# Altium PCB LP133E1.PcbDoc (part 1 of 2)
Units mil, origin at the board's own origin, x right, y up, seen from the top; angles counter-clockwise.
Board outline 3991.15 x 4704.13 mil, 4 copper layers (Top Layer, L02_GND1, L03_GND2, Bottom Layer), stack 58.396 mil thick; 74 components, 22 nets, 180 pads, 42 vias.
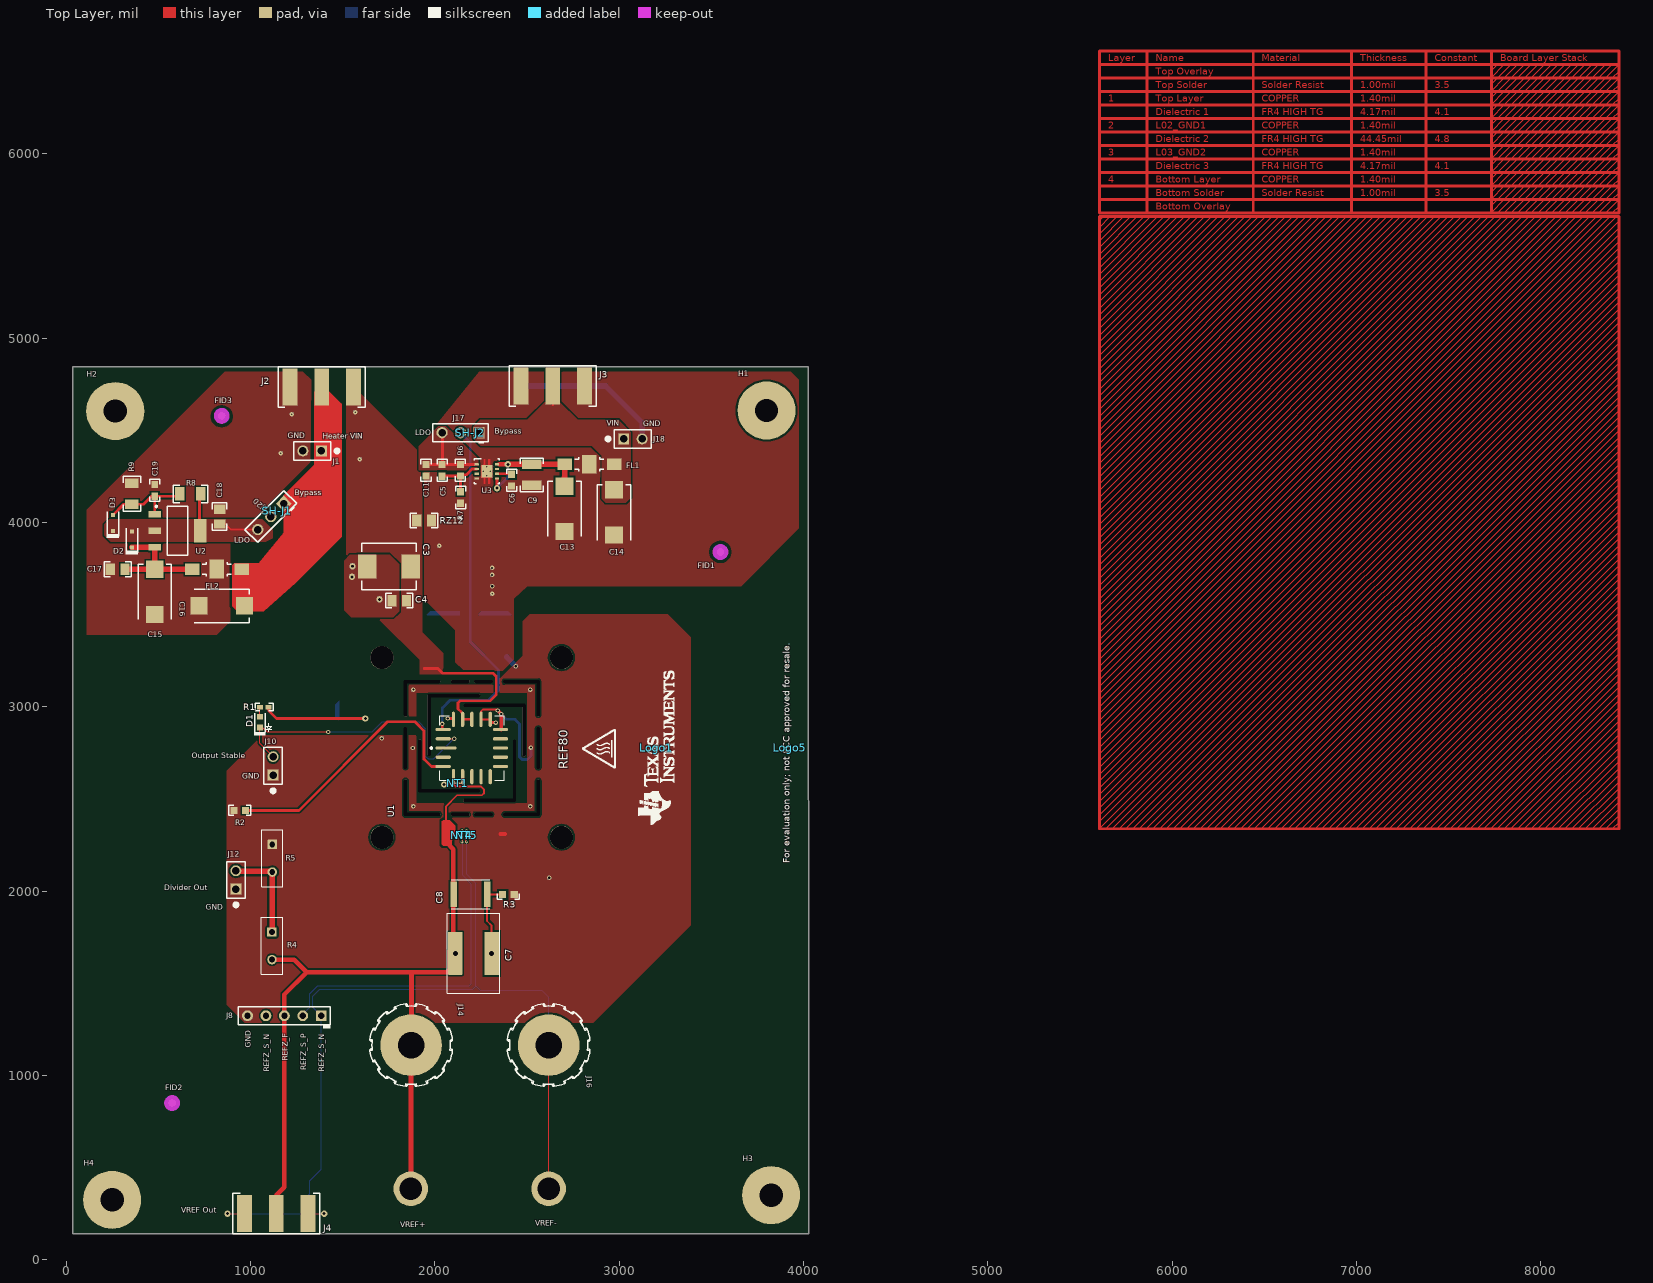
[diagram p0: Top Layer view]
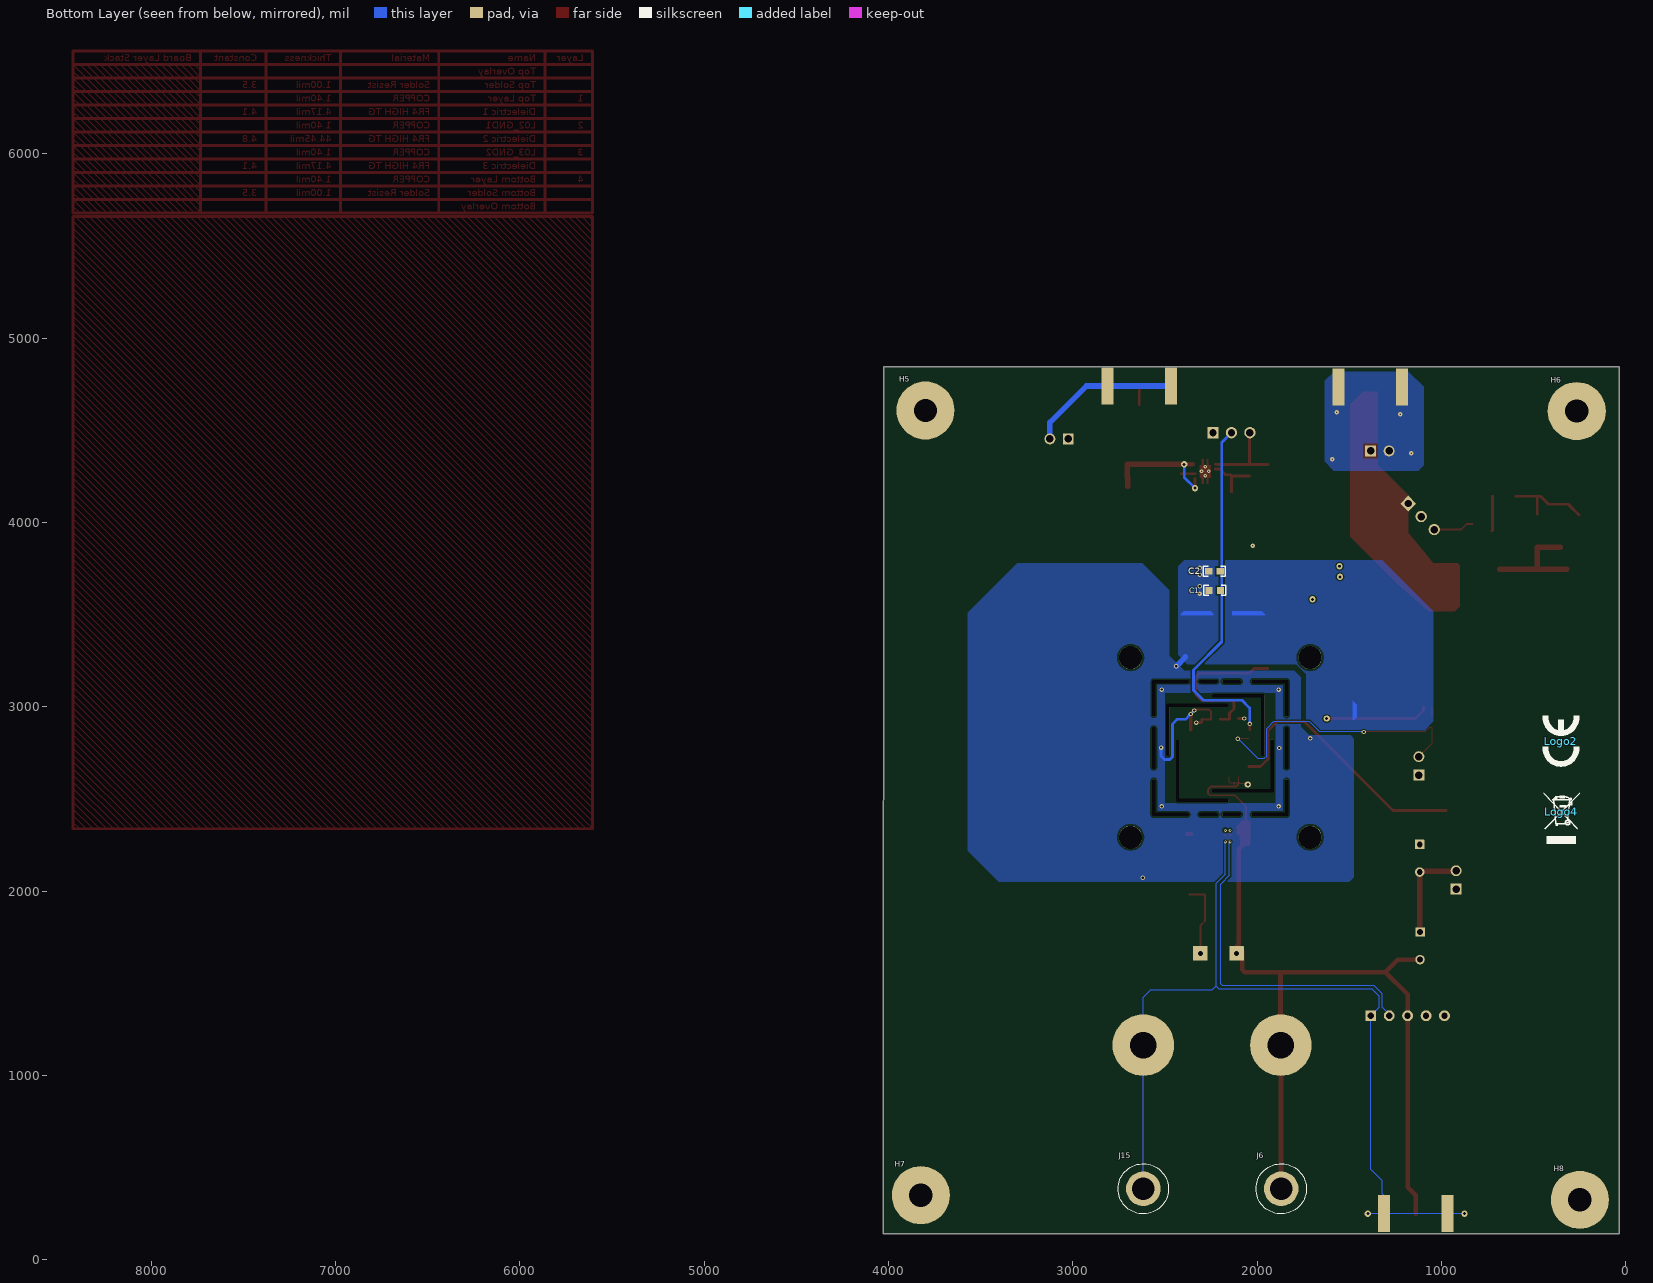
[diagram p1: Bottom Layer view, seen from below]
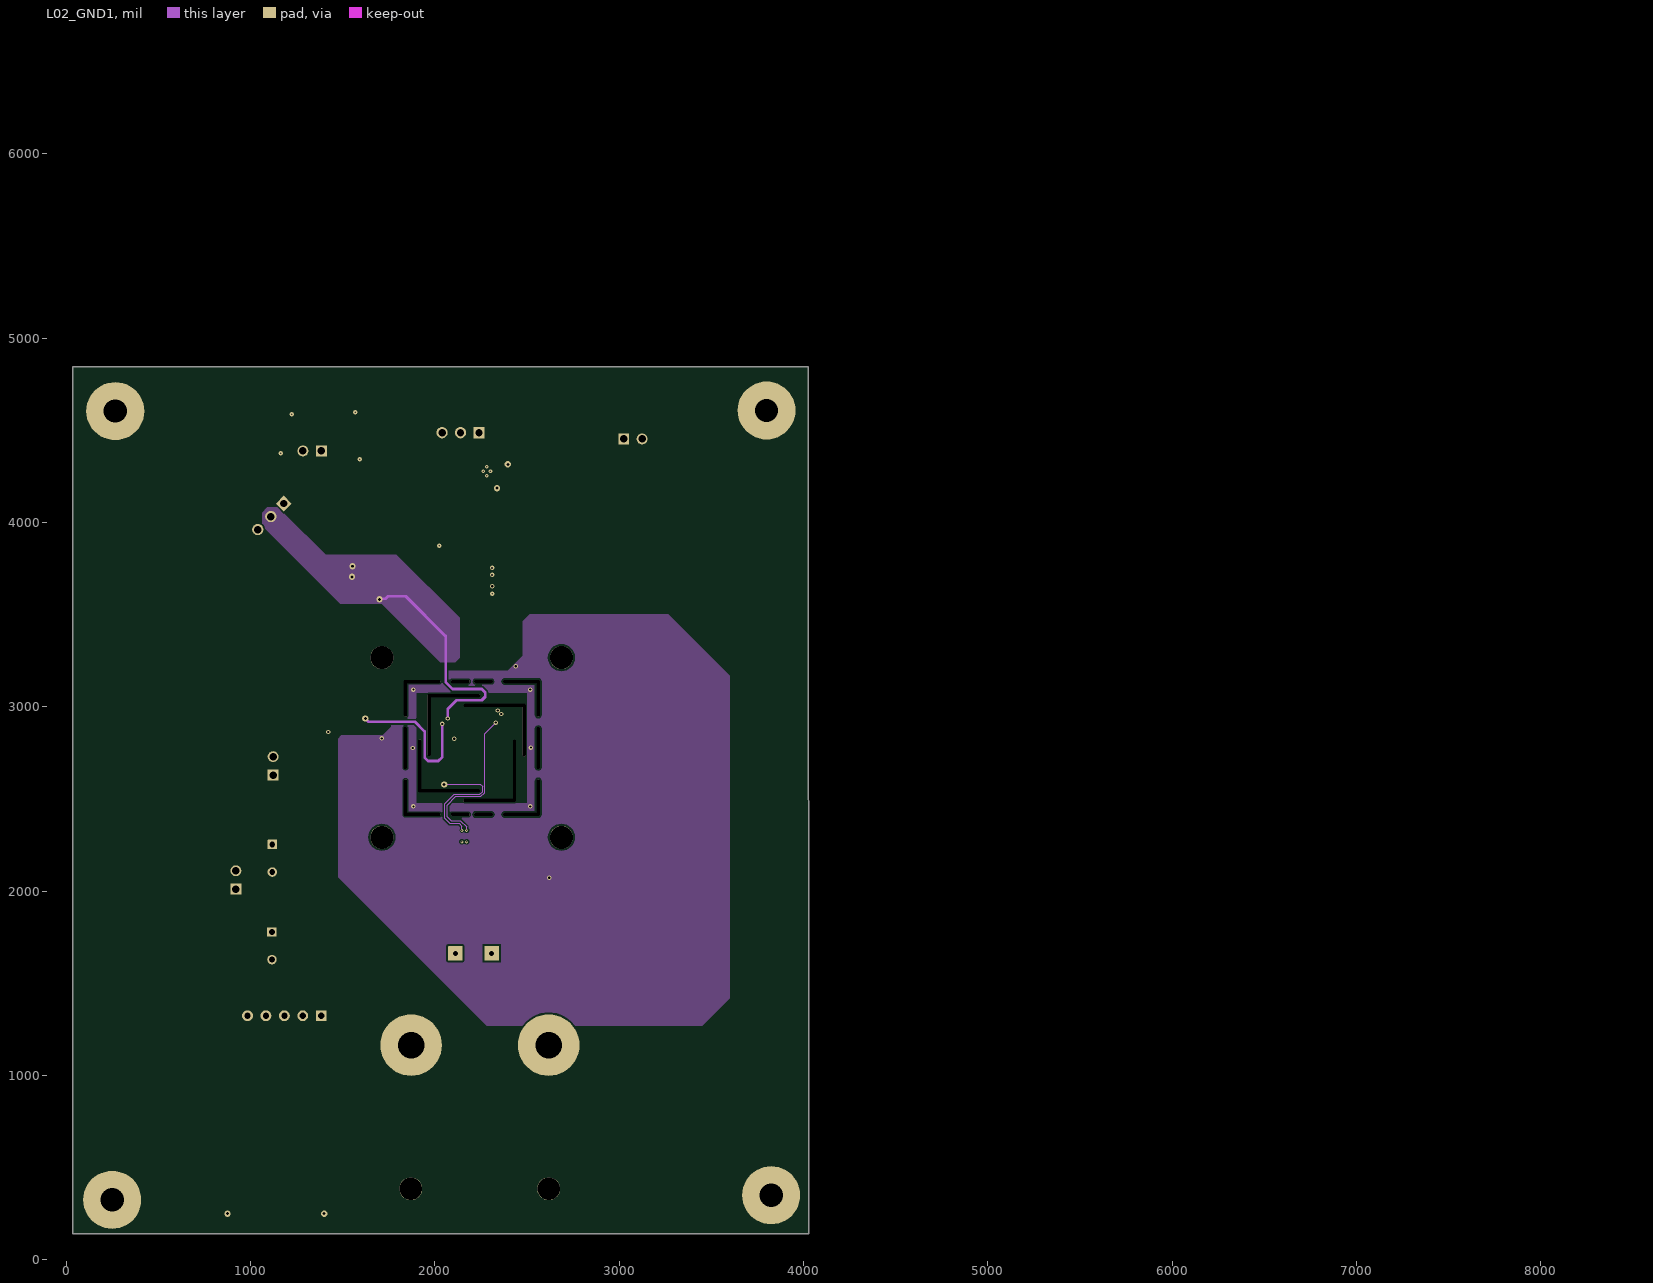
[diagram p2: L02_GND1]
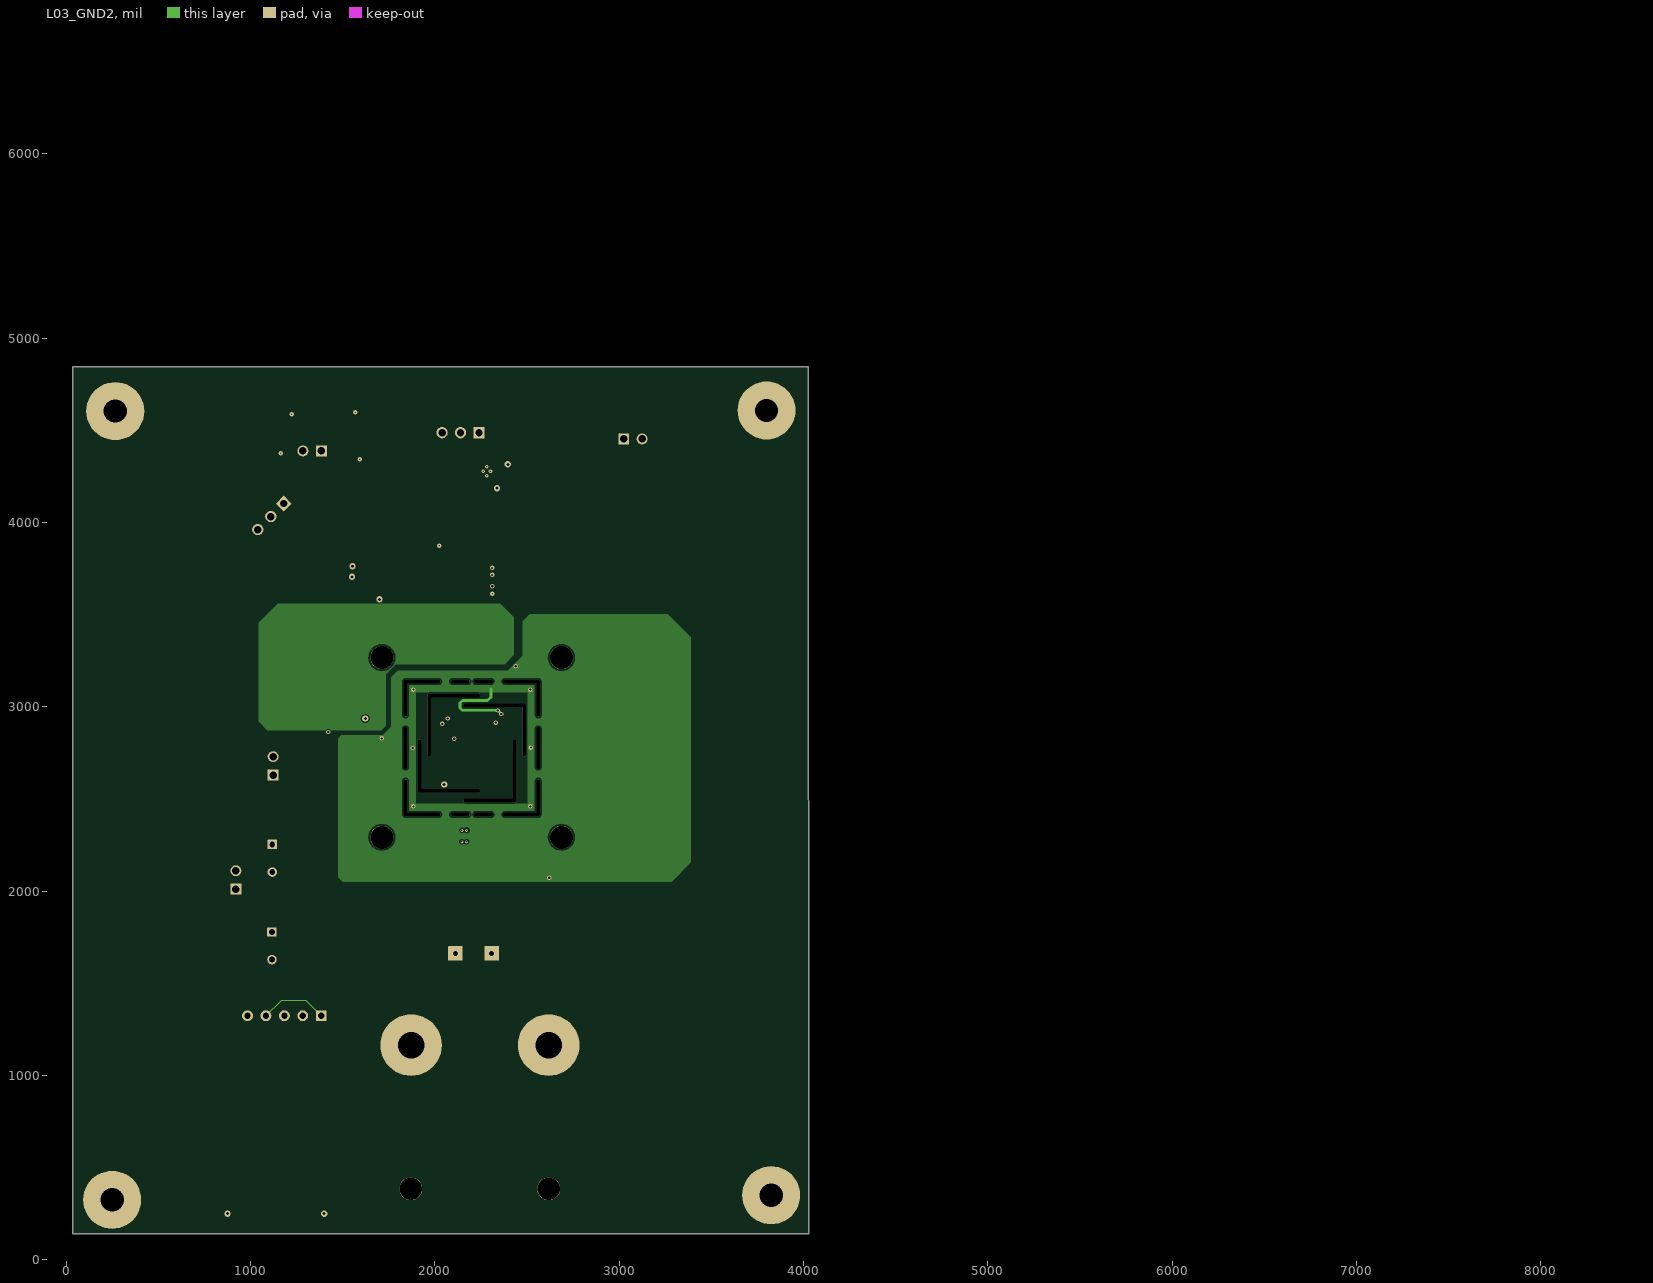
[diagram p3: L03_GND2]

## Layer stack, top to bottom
Top Solder: solder mask 1, Solder Resist, Dk 3.5
Top Layer: signal copper 1.4
Dielectric 1: prepreg 4.174, FR4 HIGH TG, Dk 4.1
L02_GND1: signal copper 1.4
Dielectric 2: core 44.448, FR4 HIGH TG, Dk 4.8
L03_GND2: signal copper 1.4
Dielectric 3: prepreg 4.174, FR4 HIGH TG, Dk 4.1
Bottom Layer: signal copper 1.4
Bottom Solder: solder mask 1, Solder Resist, Dk 3.5

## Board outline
37.25,140 36.73,4844.13 4027.14,4844.07 4027.88,140

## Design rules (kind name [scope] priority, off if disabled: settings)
AcuteAngle [All] p1: minimum=4.50000000000000E+0001 checktracksonly=FALSE
AssemblyTestPointUsage [All] p1: valid=2
BoardOutlineClearance DUT [WithinRoom('RoomDefinition')] p1: gap=5 ignorepadtopadclearanceinfootprint=FALSE
BoardOutlineClearance BoardOutlineClearance_MountingHoles [OnCopper and InComponentClass('Mounting Holes')] p2: gap=39.37 ignorepadtopadclearanceinfootprint=FALSE
BoardOutlineClearance BoardOutlineClearance_Poly [OnCopper and IsPoly] p3: gap=25 ignorepadtopadclearanceinfootprint=FALSE
BoardOutlineClearance [OnCopper and Not InComponentClass('Logo') and not InComponentClass('FiducialMark') and not InRegion(1000,500,4000,800) and not InPoly] p4: gap=40 ignorepadtopadclearanceinfootprint=FALSE
Clearance PWR1 [InNet('VIN_HTR') vs OnLayer('PWR1')] p1: gap=6 ignorepadtopadclearanceinfootprint=TRUE except(6.9: Via-Region; 7: Track-Region; 7.8: Fill-Region Region-Region; 8: Arc-Hole Track-Hole SMDPad-Hole THPad-Hole Via-Hole Fill-Hole Poly-Hole Region-Hole Text-Hole; 10: Arc-Poly Arc-Region SMDPad-Poly THPad-Poly THPad-Region Fill-Poly Poly-Poly Poly-Region; 15: Track-Poly)
Clearance [All] p2: gap=6 ignorepadtopadclearanceinfootprint=TRUE except(5: Track-Track Track-SMDPad SMDPad-Region Region-Region; 6.9: Via-Region; 7: Track-Region; 7.8: Fill-Region; 8: Arc-Hole SMDPad-Hole THPad-Region THPad-Hole Via-Hole Fill-Hole Poly-Hole Region-Hole Text-Hole; 9: Track-Hole; 10: Arc-Poly Arc-Region Track-Poly SMDPad-Poly THPad-Poly Fill-Poly Poly-Poly; 15: Poly-Region)
ComponentClearance ComponentClearance_MountingHoles_FiducialMarks [InComponentClass('Mounting Holes') vs InComponentClass('FiducialMark')] p1: gap=50 collisioncheckmode=3 verticalgap=10 showdistances=FALSE
ComponentClearance ComponentClearance_Shunt [InComponentClass('Header') vs InComponentClass('Shunt')] p2: gap=0 collisioncheckmode=3 verticalgap=0 showdistances=FALSE
ComponentClearance ComponentClearance_Logo [InComponentClass('Logo')] p3: gap=30 collisioncheckmode=3 verticalgap=10 showdistances=FALSE
ComponentClearance ComponentClearance_ScrewToNut [(HasFootprint('NY PMS 440 0025 PH')) vs (HasFootprint('Keystone_1902C'))] p4: gap=5 collisioncheckmode=3 verticalgap=10 showdistances=FALSE
ComponentClearance ComponentClearance_MountingHoles [InComponentClass('Mounting Holes')] p5: gap=100 collisioncheckmode=3 verticalgap=100000 showdistances=FALSE
ComponentClearance ComponentClearance_SmallPassives [HasFootprint('0201*') or HasFootprint('0402*') or HasFootprint('0508') or HasFootprint('0603*') or HasFootprint('0612') or HasFootprint('0805*') or HasFootprint('0815*') or HasFootprint('0830*') or HasFootprint('1206*') or HasFootprint('1210*') or HasFootprint('1808*') or HasFootprint('1812*') or HasFootprint('1825*') or HasFootprint('2010*') or HasFootprint('2220*') or HasFootprint('2225*') or HasFootprint('2512*') or HasFootprint('2728*') or HasFootprint('3518*') vs HasFootprint('0201*') or HasFootprint('0402*') or HasFootprint('0508') or HasFootprint('0603*') or HasFootprint('0612') or HasFootprint('0805*') or HasFootprint('0815*') or HasFootprint('0830*') or HasFootprint('1206*') or HasFootprint('1210*') or HasFootprint('1808*') or HasFootprint('1812*') or HasFootprint('1825*') or HasFootprint('2010*') or HasFootprint('2220*') or HasFootprint('2225*') or HasFootprint('2512*') or HasFootprint('2728*') or HasFootprint('3518*')] p6: gap=14.96 collisioncheckmode=3 verticalgap=10 showdistances=FALSE
ComponentClearance ComponentClearance_THtoSMT [IsThruComponent vs IsSMTComponent] p7: gap=30 collisioncheckmode=3 verticalgap=30 showdistances=FALSE
ComponentClearance ComponentClearance_THtoTH [IsThruComponent vs IsThruComponent] p8: gap=20 collisioncheckmode=3 verticalgap=30 showdistances=FALSE
ComponentClearance [All] p9: gap=20 collisioncheckmode=3 verticalgap=10 showdistances=FALSE
DiffPairsRouting [All] p1: maxlimit=11.47 minlimit=11.47 mostfreqgap=11.47 toplayer_minwidth=6.53 toplayer_maxwidth=6.53 toplayer_prefwidth=6.53 midlayer1_minwidth=6.53 midlayer1_maxwidth=6.53 midlayer1_prefwidth=6.53 midlayer2_minwidth=6.53 midlayer2_maxwidth=6.53 midlayer2_prefwidth=6.53 bottomlayer_minwidth=6.53 bottomlayer_maxwidth=6.53 bottomlayer_prefwidth=6.53 maxuncoupledlength=1000
FabricationTestPointUsage TestPointUsage [All] p1: valid=2 allowmultiple=FALSE
FabricationTestpoint Testpoint [All] p1: side=3 testpointundercomponent=TRUE minsize=40 maxsize=100 preferedsize=60 minholesize=0 maxholesize=40 preferedholesize=32 testpointgrid=1 allowsidetop=TRUE allowsidebottom=TRUE usegrid=TRUE gridtolerance=0.01
FanoutControl Fanout_LCC [IsLCC] p1: bgadir=Out bgaviamode=Centered fanoutstyle=Auto fanoutdirection=Alternating viagrid=1 // Fanout_LCC (Default Rule)
FanoutControl Fanout_BGA [IsBGA] p2: bgadir=Out bgaviamode=Centered fanoutstyle=Auto fanoutdirection=Alternating viagrid=1 // Fanout_BGA (Default Rule)
FanoutControl Fanout_Default [All] p4: bgadir=Out bgaviamode=Centered fanoutstyle=Auto fanoutdirection=Alternating viagrid=1 // Fanout_Default (Default Rule)
FanoutControl Fanout_Small [(CompPinCount < 5)] p5: bgadir=Out bgaviamode=Centered fanoutstyle=Auto fanoutdirection=OutThenIn viagrid=1 // Fanout_Small (Default Rule)
HoleSize [All] p1: absolutevalues=TRUE maxlimit=251 minlimit=7.87 maxpercent=80.000 minpercent=20.000
MinimumAnnularRing MinimumAnnularRing_ThermalPadVias [IsVia and InAnyComponent] p1: minimumring=5.91
MinimumAnnularRing [All] p2: minimumring=7.87
MinimumSolderMaskSliver MinimumSolderMaskSliver_Logo [InComponentClass('Logo') vs InComponentClass('Logo')] p1: minsoldermaskwidth=0.7
MinimumSolderMaskSliver [All] p2: minsoldermaskwidth=3.94
PlaneConnect [All] p1: planeconnectstyle=Relief reliefexpansion=10 reliefentries=4 reliefconductorwidth=10 reliefairgap=10
PolygonConnect [All] p1: connectstyle=Direct reliefconductorwidth=10 reliefentries=4 polygonreliefangle="90 Angle" airgapwidth=10
RoomDefinition LP133E1_Hardware [InComponentClass('LP133E1_Hardware')] p1: confinementstyle=ConfineIn formatcopy=TRUE lockcomponents=FALSE outline 291.49,1189.73 1196.62,1189.73 1196.62,301.8 291.49,301.8
RoutingVias ThermalPadVias [IsVia and InAnyComponent] p1: holewidth=7.87 width=19.68 viastyle="Through Hole" minholewidth=7.87 minwidth=19.68 maxholewidth=12.99 maxwidth=23.62
RoutingVias [All] p2: holewidth=16 width=34 viastyle="Through Hole" minholewidth=7.87 minwidth=24 maxholewidth=40 maxwidth=65
SMDEntry [All] p1: side=TRUE corner=TRUE anyangle=FALSE
SMDToCorner [All] p1: distance=0
SilkToBoardRegionClearance [Not ((IsComment or IsDesignator) And (Hide <> 'False')) and not InRegion(1000,500,4000,800)] p1:
SilkToSilkClearance SilkToSilkClearance_Pb-FreeLogo [(HasFootprint('Pb-Free_Overlay_Medium') OR HasFootprint('Pb-Free_Overlay_Small')) vs (HasFootprint('Pb-Free_Overlay_Medium') OR HasFootprint('Pb-Free_Overlay_Small'))] p1: silktosilkclearance=0
SilkToSilkClearance [All] p2: silktosilkclearance=3.94
SilkToSolderMaskClearance SilkToComponentPadClearance [(IsPad or IsFill or IsRegion) and InAnycomponent] p1: minsilkscreentomaskgap=5 clearancetoexposedcopper=TRUE
SilkToSolderMaskClearance "Silk to Solder Mask Opening" [All] p2: minsilkscreentomaskgap=3.94 clearancetoexposedcopper=FALSE
SolderMaskExpansion [All] p1: expansion=1.97 istentingtop=FALSE
UnRoutedNet [All] p1: checkbadconnections=TRUE
Width [All] p1: maxlimit=100 minlimit=6 preferedwidth=8 checkconnectedcopper=TRUE
14 further rules are at their usual default settings.

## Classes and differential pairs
component class "Mounting Holes": H1 H2 H3 H4
component class LP133E1_Hardware: !PCB FID1 FID2 FID3 H1 H2 H3 H4 H5 H6 H7 H8 Logo1 Logo2 Logo3 Logo4 Logo5 ZZ1 ZZ2 ZZ3 ZZ4
component class Header: J1 J8 J10 J12 J18
component class LP133E1: 1 C1 C2 C3 C4 C5 C6 C7 C8 C9 C11 C13 C14 C15 C16 C17 C18 C19 D1 D2 D3 FL1 FL2 J1 J2 J3 J4 J6 J8 J10 J12 J14 J15 J16 J17 J18 J20 NT1 NT4 NT5 R1 R2 R3 R4 R5 R6 R7 R8 R9 RZ12 SH-J1 SH-J2 U1 U2 U3
component class Logo: Logo1
component class FiducialMark: FID1 FID2 FID3
component class AssemblyNote: ZZ1 ZZ2 ZZ3 ZZ4

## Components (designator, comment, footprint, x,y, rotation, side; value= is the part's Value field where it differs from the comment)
C1 "GRJ188R71E105KE11D" 0603 2230.37,3631.07 r0 bottom value=1uF
C2 "CL10A104KA8NNNC" 0603 2232.18,3734.98 r0 bottom value=0.1uF
C3 "TAJV226K050RNJ" 7361-38 1751.94,3761.5 r0 top value=22uF
C4 "CL21B105KBFNFNE" 0805_HV 1807.42,3575.7 r0 top value=1uF
C5 "C0603C103F3GACTU" 0603 2039.83,4282.19 r270 top value=0.01uF
C6 "C0603C103F3GACTU" 0603 2416.66,4229.57 r270 top value=0.01uF
C7 "MKS2B051001N00JSSD" FP-MKS2B051001N00JSSD_RADIAL-MFG 2210.01,1662.11 r0 top value=10µF
C8 "16MU106MC44532" 1812 2192.95,1982.14 r0 top value=10UF
C9 "CL32B106KBJNNWE" 1210_270 2525.72,4257.87 r270 top value=10uF
C11 "GRM188R61E106KA73D" 0603 1952.46,4282.72 r270 top value=10uF
C13 "20TQC47MYF" 7343-20 2703.61,4073.84 r270 top value=47uF
C14 "20TQC47MYF" 7343-20 2972.54,4054.15 r270 top value=47uF
C15 "20TQC47MYF" 7343-20 480.92,3623.46 r270 top value=47uF
C16 "20TQC47MYF" 7343-20 844.21,3547.28 r180 top value=47uF
C17 "C2012X6S1H105K125AB" 0805_HV 279.85,3746.41 r180 top value=1uF
C18 "C2012X6S1H105K125AB" 0805_HV 832.63,4031.43 r90 top value=1uF
C19 "GRM188R61E106KA73D" 0603 480.92,4173.55 r270 top value=10uF
D1 "HSMA-C190" HSMx-C190_Amber 1051.45,2916.44 r270 top value=Amber
D2 "CUS10S30,H3F" SOD-323 357.15,3907.42 r90 top value=20V
D3 "CUS10S30,H3F" SOD-323 254.24,3996.98 r90 top value=20V
FID1 "Fiducial" Fiducial10-20 3549.88,3839.39 r0 top
FID2 "Fiducial" Fiducial10-20 575,850 r0 top
FID3 "Fiducial" Fiducial10-20 844.21,4578.04 r0 top
FL1 "NFE61PT472C1H9L" 2706 2838.69,4315.73 r0 top value=4700pF
FL2 "NFE61PT472C1H9L" 2706 818.15,3746.3 r0 top value=4700pF
H1 "NY PMS 440 0025 PH" "NY PMS 440 0025 PH" 3800,4607.26 r0 top
H2 "NY PMS 440 0025 PH" "NY PMS 440 0025 PH" 266.73,4603.97 r0 top
H3 "NY PMS 440 0025 PH" "NY PMS 440 0025 PH" 3825,350 r0 top
H4 "NY PMS 440 0025 PH" "NY PMS 440 0025 PH" 250,325 r0 top
H5 "1902C" Keystone_1902C 3800.13,4607.27 r180 bottom
H6 "1902C" Keystone_1902C 266.86,4603.98 r180 bottom
H7 "1902C" Keystone_1902C 3825.13,350.01 r180 bottom
H8 "1902C" Keystone_1902C 250.36,325.01 r180 bottom
J1 "5-146261-1" CONN_5-146261-1 1334.72,4387.76 r180 top
J2 "142-0701-851" EMERSON_142-0701-851 1386.76,4844.11 r0 top
J3 "142-0701-851" EMERSON_142-0701-851 2640.07,4850 r0 top
J4 "142-0701-851" EMERSON_142-0701-851 1140,140 r180 top
J6 "72918" FP-72918_CONNECTOR_BANANA_PLUG-MFG 1869.98,384.74 r180 bottom locked
J8 "800-10-005-10-001000" Mill-Max_800-10-005-10-001000 1184.11,1323.66 r180 top
J10 "5-146261-1" CONN_5-146261-1 1123.07,2679.12 r90 top
J12 "5-146261-1" CONN_5-146261-1 921.41,2060.17 r90 top
J14 "111-0702-001" Emerson_111-0702-001 1871.95,1164.22 r270 top
J15 "72918" FP-72918_CONNECTOR_BANANA_PLUG-MFG 2618.01,384.74 r180 bottom locked
J16 "111-0703-001" Emerson_111-0703-001 2618.01,1164.22 r270 top
J17 "HTSW-103-09-G-S" Samtec_HTSW-103-09-x-S 2139.83,4486.75 r180 top
J18 "5-146261-1" CONN_5-146261-1 3075,4452.98 r0 top
J20 "HTSW-103-09-G-S" Samtec_HTSW-103-09-x-S 1110.55,4031.79 r225 top
Logo1 "Texas Instruments" TI_Stacked_Overlay_Small 3201.87,2777.53 r90 top
Logo2 "CE Mark" CE_Mark_5mm 352.15,2812.45 r90 bottom
Logo3 "FCC disclaimer" FCC_disclaimer -3342.4,1916.61 r180 bottom
Logo4 "WEEE logo" WEEE_Minimum 350,2429.53 r180 bottom
Logo5 "FCC disclaimer" FCC_disclaimer 3925,2778.58 r90 top
NT1 "Net-Tie" Net-Tie_10mil 2124.6,2584.87 r0 top net-tie
NT4 "Net-Tie" Net-Tie_10mil 2147.04,2302.95 r270 top net-tie
NT5 "Net-Tie" Net-Tie_10mil 2172.83,2302.95 r270 top net-tie
R1 "CRCW04021K00JNED" 0402 1075.08,2997.93 r0 top value=1.0k
R2 "RT0603DRE07135KL" 0603 942.29,2437.68 r0 top value=135k
R3 "ERJ-3RQFR22V" 0603 2399.6,1982.14 r180 top value=0.22
R4 "Y0062100K000T9L" FP-Y0062100K000T9L_RADIAL-MFG 1116.69,1702.91 r270 top value=100k
R5 "Y0062100K000T9L" FP-Y0062100K000T9L_RADIAL-MFG 1118.63,2177.93 r270 top value=100k
R6 "RC0603FR-0739KL" 0603 2139.34,4283.27 r90 top value=39.0k
R7 "RC0603JR-073K3L" 0603 2139.83,4134.86 r90 top value=3.3k
R8 "CRCW1206100RFKEA" 1206 674.45,4154.67 r0 top value=100
R9 "CRCW12061K10JNEA" 1206 357.09,4155.83 r270 top value=1.1k
RZ12 "CRCW08050000Z0EA" 0805_HV 1941.75,4010.22 r180 top value=0
SH-J1 "QPC02SXGN-RC" FP-QPC02SXGN-RC_JUMPER-MFG 1144.78,4061.97 r45 top
SH-J2 "QPC02SXGN-RC" FP-QPC02SXGN-RC_JUMPER-MFG 2192.65,4487.72 r180 top
U1 "REF80000A1NAJ" NAJ0020A-IPC_C 2201.15,2776.12 r90 top locked
U2 "LM317AEMP/NOPB" DCY0004A_N 603.95,3954.66 r0 top
U3 "TPS7A4901DRBR" DRB0008A 2282.44,4276.77 r0 top
ZZ1 "This Assembly Note is for PCB labels only" AssemblyNoteLabel -1560.47,-1146.06 r0 top
ZZ2 "These assemblies are ESD sensitive, ESD precautions shall be observed." AssemblyNote -1560.47,-1254.94 r0 top
ZZ3 "These assemblies must be clean and free from flux and all contaminants. Use of no clean flux is not acceptable." AssemblyNote -1560.47,-1343.5 r0 top
ZZ4 "These assemblies must comply with workmanship standards IPC-A-610 Class 2, unless otherwise specified." AssemblyNote -1560.47,-1432.06 r0 top

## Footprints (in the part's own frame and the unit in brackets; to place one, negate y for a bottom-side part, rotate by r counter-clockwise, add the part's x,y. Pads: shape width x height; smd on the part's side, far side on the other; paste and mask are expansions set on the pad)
0402 [mm] "0402 from SM-752 data"
  rect 0.8x0.6 smd: 1(-0.6,0) 2(0.6,0)
  silkscreen extent -1.22,-0.52 1.22,0.52, body extent -0.55,-0.3 0.55,0.3, height 0.6
0603 [mm] "0603 from SM-752 data"
  rect 1x0.95 smd: 1(-0.8,0) 2(0.8,0)
  silkscreen extent -1.52,-0.69 1.52,0.69, body extent -0.87,-0.47 0.87,0.47, height 1
0805_HV [mil] "0805 with 30mil clearance between pads"
  rect 50x63 smd: 1(-40,0) 2(40,0)
  silkscreen extent -74,-40 74,40, body extent -43,-29 43,29, height 57
1206 [mm] "1206 from SM-752 data"
  rect 1.3x1.85 smd: 1(-1.45,0) 2(1.45,0)
  silkscreen extent -2.4,-1.21 2.4,1.21, body extent -1.7,-0.9 1.7,0.9, height 1.35
1210_270 [mm] "1210"
  rect 1.3x2.7 smd: 1(-1.45,0) 2(1.45,0)
  silkscreen extent -2.32,-1.57 2.32,1.57, body extent -1.7,-1.35 1.7,1.35, height 2.7
1812 [mm]
  rect 0.908x3.5 smd mask+0.05: 1(-2.304,0) 2(2.304,0)
  silkscreen extent -2.65,-2 2.65,2, body extent -2.4,-1.75 2.4,1.75, height 2.8
2706 [mm] "SMD, 3-Leads, Body 6.8x1.6mm"
  rect 2x1.6 smd: 1(-3.4,0) 3(3.4,0)
  rect 2x2.6 smd: 2(0,0)
  silkscreen extent -2,-0.95 2,0.95, body extent -3.65,-0.95 3.65,0.95, height 1.9
7343-20 [mm] "Medium density IPC, based on Kemet case V from T495 datasheet"
  rect 2.37x2.43 smd: 1(-3.12,0) 2(3.12,0)
  silkscreen extent -3.8,-2.3 3.8,2.3, body extent -3.8,-2.3 3.8,2.3, height 2
7361-38 [mm] "Medium density IPC based on AVX dimensions for TPS series"
  rect 2.55x3.3 smd mask+0.05: 1(-2.975,0) 2(2.975,0)
  silkscreen extent -3.75,-3.2 3.75,3.2, body extent -3.75,-3.15 3.75,3.15, height 3.8
AssemblyNote [mil] "Assembly Note"
AssemblyNoteLabel [mil] "Assembly Note for PCB Labels"
CE_Mark_5mm [mil] "Minimum text height for CE Mark"
  silkscreen extent -138,-98 138,98
CONN_5-146261-1 [mm] "Sullins"
  rect 1.5x1.5 hole 1.02: 1(-1.27,0)
  round 1.5 hole 1.02: 2(1.27,0)
  silkscreen extent -3.68,-1.27 2.54,1.27, body extent -2.51,-1.27 2.51,1.27, height 10.87
DCY0004A_N [mm] "SOT223/SC73, 4-Leads, Body 6.5x3.5mm, Pitch 2.3mm, Lead Span 7mm, IPC Medium Density"
  rrect11% 1.75x0.9 smd: 1(-3.125,2.3) 2(-3.125,0) 3(-3.125,-2.3)
  rrect6% 1.75x3.2 smd: 4(3.125,0)
  silkscreen extent -3.02,-3.35 1.4,3.47, body extent -3.48,-3.25 3.48,3.25, height 1.68
DRB0008A [mm] "VSON-8"
  rrect32% 0.6x0.31 smd: 1(-1.4,0.975) 2(-1.4,0.325) 3(-1.4,-0.325) 4(-1.4,-0.975) 5(1.4,-0.975) 6(1.4,-0.325) 7(1.4,0.325) 8(1.4,0.975)
  rrect7% 1.5x1.75 smd paste-0.75: 9(0,0)
  Top Layer region: -0.7,-0.875 -0.49,-0.875 -0.471,-0.879 -0.455,-0.89 -0.444,-0.906 -0.44,-0.925 -0.44,-0.925 -0.44,-1.65 -0.436,-1.669 -0.425,-1.685 -0.409,-1.696 -0.39,-1.7 -0.39,-1.7 -0.26,-1.7 -0.241,-1.696 -0.225,-1.685 -0.214,-1.669 -0.21,-1.65 -0.21,-1.65 -0.21,-0.925 -0.206,-0.906 -0.195,-0.89 -0.179,-0.879 -0.16,-0.875 -0.16,-0.875 0.16,-0.875 0.179,-0.879 0.195,-0.89 0.206,-0.906 0.21,-0.925 0.21,-0.925 0.21,-1.65 0.21,-1.65 0.214,-1.669 0.225,-1.685 0.241,-1.696 0.26,-1.7 0.26,-1.7 0.39,-1.7 0.409,-1.696 0.425,-1.685 0.436,-1.669 0.44,-1.65 0.44,-1.65 0.44,-0.925 0.444,-0.906 0.455,-0.89 0.471,-0.879 0.49,-0.875 0.49,-0.875 0.7,-0.875 0.719,-0.871 0.735,-0.86 0.746,-0.844 0.75,-0.825 0.75,-0.825 0.75,0.825 0.746,0.844 0.735,0.86 0.719,0.871 0.7,0.875 0.7,0.875 0.49,0.875 0.471,0.879 0.455,0.89 0.444,0.906 0.44,0.925 0.44,0.925 0.44,1.65 0.436,1.669 0.425,1.685 0.409,1.696 0.39,1.7 0.39,1.7 0.26,1.7 0.241,1.696 0.225,1.685 0.214,1.669 0.21,1.65 0.21,1.65 0.21,1.65 0.21,0.925 0.206,0.906 0.195,0.89 0.179,0.879 0.16,0.875 0.16,0.875 -0.16,0.875 -0.179,0.879 -0.195,0.89 -0.206,0.906 -0.21,0.925 -0.21,0.925 -0.21,1.65 -0.214,1.669 -0.225,1.685 -0.241,1.696 -0.26,1.7 -0.26,1.7 -0.39,1.7 -0.409,1.696 -0.425,1.685 -0.436,1.669 -0.44,1.65 -0.44,1.65 -0.44,0.925 -0.444,0.906 -0.455,0.89 -0.471,0.879 -0.49,0.875 -0.49,0.875 -0.7,0.875 -0.719,0.871 -0.735,0.86 -0.746,0.844 -0.75,0.825 -0.75,0.825 -0.75,-0.825 -0.746,-0.844 -0.735,-0.86 -0.719,-0.871 -0.7,-0.875
  silkscreen extent -1.73,-1.73 1.73,1.73, body extent -1.5,-1.5 1.5,1.5, height 0.77
Emerson_111-0702-001 [mm] "Receptacle, 1x1 Position, Dia 10.74mm, Red, TH"
  round 8.5 hole 3.658: 1(0,0)
  silkscreen extent -5.69,-5.69 5.69,5.69, body extent -5.69,-5.69 5.69,5.69, height 26.47
Emerson_111-0703-001 [mm] "Receptacle, 1x1 Position, Dia 10.74mm, Black, TH"
  round 8.5 hole 3.658: 1(0,0)
  silkscreen extent -5.69,-5.69 5.69,5.69, body extent -5.69,-5.69 5.69,5.69, height 26.48
EMERSON_142-0701-851 [mil] "Cinch Connectivity"
  rect 80x200 smd mask+1: 1(0,-110) 2(-172.5,-110) 3(172.5,-110)
  rect 66x200 smd far side mask+1: 4(172.5,-110) 5(-172.5,-110)
  silkscreen extent -235,-220 235,0, body extent -190,-195 190,387, height 155
FCC_disclaimer [mil]
Fiducial10-20 [mm]
  round 1 smd mask+0.5: 1(0,0)
  Top Layer keep-out circle w1.178: c0,0 r0.5
FP-72918_CONNECTOR_BANANA_PLUG-MFG [mm]
  round 4.75 / inner round 3.15 / far side round 4.75 hole 3.15 paste+0 mask+0: 1(0,0)
  silkscreen extent -3.46,-3.46 3.46,3.46, body extent -2.69,-3 2.69,3, height 22.04
FP-MKS2B051001N00JSSD_RADIAL-MFG [mm]
  rrect8% 2x5.908 / inner rrect8% 2x2 / far side rrect8% 2x2 hole 0.7 paste-1000 mask+0: 1(-2.5,0)
  rect 2x5.908 / inner rect 2x2 / far side rect 2x2 hole 0.7 paste-1000 mask+0: 2(2.5,0)
  silkscreen extent -3.6,-5.5 3.6,5.5, body extent -3.7,-5.6 3.7,5.6, height 0.25
FP-QPC02SXGN-RC_JUMPER-MFG [mil]
  body extent -106,-56 106,56, height 10
FP-Y0062100K000T9L_RADIAL-MFG [mm]
  rrect8% 1.3x1.3 hole 0.8 paste-1000 mask+0: 1(-1.905,0)
  round 1.3 hole 0.8 paste-1000 mask+0: 2(1.905,0)
  silkscreen extent -3.94,-1.46 3.94,1.46, body extent -4.04,-1.56 4.04,1.56, height 0.25
HSMx-C190_Amber [mm] "SMD, 2-Leads, Body 1.6x0.8mm"
  rect 0.8x0.8 smd: 1(-0.75,0) 2(0.75,0)
  silkscreen extent -1.2,-0.8 1.85,0.8, body extent -0.85,-0.45 0.85,0.45, height 0.9
Keystone_1902C [mil] "Hex Standoff, 4-40 threaded, nylon"
  round 1 on Mech4: 0(0,0)
  body extent -145,-126 146,126, height 501
Mill-Max_800-10-005-10-001000 [mm] "Mill-Max"
  rect 1.5x1.5 hole 0.85: 1(-5.08,0)
  round 1.5 hole 0.85: 2(-2.54,0) 3(0,0) 4(2.54,0) 5(5.08,0)
  silkscreen extent -6.35,-1.27 6.35,1.78, body extent -6.35,-1.27 6.35,1.27, height 8.13
NAJ0020A-IPC_C [mm]
  rrect100% 0.45x2.9 smd paste+0 mask+0: 1(0,3.55)
  rrect100% 0.45x2.1 smd paste+0 mask+0: 2(-1.27,3.95) 3(-2.54,3.95) 9(-2.54,-3.95) 10(-1.27,-3.95) 11(0,-3.95) 12(1.27,-3.95) 13(2.54,-3.95) 19(2.54,3.95) 20(1.27,3.95)
  rrect100% 2.1x0.45 smd paste+0 mask+0: 4(-3.95,2.54) 5(-3.95,1.27) 6(-3.95,0) 7(-3.95,-1.27) 8(-3.95,-2.54) 14(3.95,-2.54) 15(3.95,-1.27) 16(3.95,0) 17(3.95,1.27) 18(3.95,2.54)
  silkscreen extent -4.44,-4.44 4.44,5.7, body extent -5.1,-5.1 5.1,5.1, height 0.25
Net-Tie_10mil [mil] "10mil net tie, no solder mask opening, no solder paste"
  rect 10x10 smd paste-5 mask-5: 1(-10,0) 2(10,0)
  Top Layer region: -6,5 6,5 6,-5 -6,-5
"NY PMS 440 0025 PH" [mm] "4-40 nylon screw and mounting hole"
  round 8 hole 3.2: 1(0,0)
  body extent -3.3,-3.3 3.3,3.3, height 2.69
Samtec_HTSW-103-09-x-S [mm] "Header, 3x1, 2.54mm, TH"
  rect 1.55x1.55 hole 1.02: 1(-2.54,0)
  round 1.55 hole 1.02: 2(0,0) 3(2.54,0)
  silkscreen extent -3.81,-1.24 3.81,1.5, body extent -3.81,-1.24 3.81,1.24, height 8.38
SOD-323 [mm] "NXP recommended land pattern"
  rect 0.6x0.6 smd paste-0.05: 1(-1.1,0) 2(1.1,0)
  silkscreen extent -2.06,-0.86 1.53,0.86, body extent -1.3,-0.67 1.3,0.68, height 1.1
TI_Stacked_Overlay_Small [mil]
  silkscreen extent -418,-98 418,98
WEEE_Minimum [mil] "WEEElie bin"
  silkscreen extent -95,-172 99,104

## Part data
C1: library part CMP-0079720-1, "CAP, CERM, 1 µF, 25 V,+/- 10%, X7R, 0603", Cap_Case=0603, Manufacturer=MuRata, Supplier Part Number 1=490-10888-1-ND, TempCo=X7R, Tolerance_%=10%, Value2=25V, ValueDisplayed=1µF
C2: library part CMP-0085577-2, "CAP, CERM, 0.1 µF, 25 V,+/- 10%, X5R, 0603", Cap_Case=0603, Manufacturer="Samsung Electro-Mechanics", TempCo=X5R, Tolerance_%=10%, Value2=25V, ValueDisplayed=0.1µF
C3: library part CMP-0064995-1, "CAP, TA, 22 uF, 50 V, +/- 10%, 0.6 ohm, SMD", Cap_Case=7361-38, Manufacturer=AVX, Supplier Part Number 1=478-5811-1-ND, Tolerance_%=10%, Value1="0.6 ohm", Value2=50V, ValueDisplayed=22uF
C4: library part CMP-0080611-1, "CAP, CERM, 1 µF, 50 V,+/- 10%, X7R, 0805", Cap_Case=0805, Manufacturer=Samsung, Supplier Part Number 1=1276-2928-1-ND, TempCo=X7R, Tolerance_%=10%, Value2=50V, ValueDisplayed=1µF
C5 C6: library part CMP-0079995-1, "CAP, CERM, 0.01 µF, 25 V,+/- 1%, C0G/NP0, 0603", Cap_Case=0603, Manufacturer=Kemet, Supplier Part Number 1=399-8985-1-ND, TempCo=C0G/NP0, Tolerance_%=1%, Value2=25V, ValueDisplayed=0.01µF
C7: library part CMP-0096040-1, "10 µF Film Capacitor 30V 50V Polyester, Polyethylene Terephthalate (PET), Metallized Radial", Digikey Part Number=1928-1631-ND, Manufacturer=WIMA, Mouser Part Number=505-MKS2B051001N00JS, Operating Temperature Range="-55°C to +105°C", Tolerance_%=5%, ValueDisplayed=10uF
C8: library part CMP-0012475-2, "CAP FILM 10UF 20% 16VDC 1812", Cap_Case=1812, Manufacturer=Rubycon, Tolerance_%=20%, Value1=Unknown, Value2=16V, ValueDisplayed=10UF
C9: library part CMP-0079201-1, "CAP, CERM, 10 µF, 50 V,+/- 10%, X7R, 1210", Cap_Case=1210, Manufacturer="Samsung Electro-Mechanics", Supplier Part Number 1=1276-3388-1-ND, TempCo=X7R, Tolerance_%=10%, Value1="0.005 ohm", Value2=50V, ValueDisplayed=10µF
C11 C19: library part CMP-0860569-1, "CAP, CERM, 10 µF, 25 V,+/- 10%, X5R, 0603", Cap_Case=0603, Manufacturer=MuRata, TempCo=X5R, Tolerance_%=10%, Value2=25V, ValueDisplayed=10µF
C13 C14 C15 C16: library part CMP-0012618-4, "CAP, Tantalum Polymer, 47 uF, 20 V, +/- 20%, 0.055 ohm, 7343-20 SMD", Cap_Case=7343-20, Manufacturer=Panasonic, Supplier Part Number 1=P16249CT-ND, Tolerance_%=20%, Value1="0.055 ohm", Value2=20V, ValueDisplayed=47uF
C17 C18: library part CMP-0007855-1, "CAP, CERM, 1 uF, 50 V, +/- 10%, X6S, 0805", Cap_Case=0805, Manufacturer=TDK, Supplier Part Number 1=445-7595-1-ND, TempCo=X6S, Tolerance_%=10%, Value1="0.008782 ohm", Value2=50V, ValueDisplayed=1uF
D1: library part CMP-0003041-3, "LED, Amber, SMD", Color=Amber, Manufacturer=Avago, Power_TotalModule=60mW, Value1=0.06W, Value2=1.9V
D2 D3: library part CMP-0028893-2, "Diode, Schottky, 20 V, 1 A, SOD-323", Manufacturer=Toshiba, Value1=1A, Value2=0.37V
FID1 FID2 FID3: library part CMP-0077181-1, "Fiducial mark.  There is nothing to buy or mount.", Manufacturer=N/A
FL1 FL2: library part CMP-0001717-2, "Filter LC High freq 4700PF, 2706", Manufacturer=MuRata, Supplier Part Number 1=490-2554-1-ND
H1 H2 H3 H4: library part CMP-0003617-1, "Machine Screw, Round, #4-40 x 1/4, Nylon, Philips panhead", Manufacturer="B&F Fastener Supply", Supplier Part Number 1=H542-ND
H5 H6 H7 H8: library part CMP-0003610-1, "Standoff, Hex, 0.5\"L #4-40 Nylon", Manufacturer=Keystone, Supplier Part Number 1=36-1902C-ND
J1 J10 J12 J18: library part CMP-0054947-1, "Header, 100mil, 2x1, Gold, TH", Manufacturer="TE Connectivity"
J2 J3 J4: library part CMP-0055822-3, "Connector, End launch SMA, 50 ohm, SMT", Manufacturer="Cinch Connectivity", Supplier Part Number 1=J658-ND
J6 J15: library part CMP-0092456-1, "Banana Plug Connector Standard Banana Threaded, External (Nut) -", Current_A=36A, Digikey Part Number=501-1200-ND, Manufacturer="Pomona Electronics", Mouser Part Number=565-72918, Operating Temperature Range=to
J8: library part CMP-0055088-1, "Header, 100mil, 5x1, TH", Manufacturer=Mill-Max, Supplier Part Number 1=ED7205-ND
J14: library part CMP-0075036-1, "Binding Post, Red, TH", Manufacturer="Cinch Connectivity", Supplier Part Number 1=J10125-ND
J16: library part CMP-0075035-1, "Binding Post, Black, TH", Manufacturer="Cinch Connectivity", Supplier Part Number 1=J10126-ND
J17 J20: library part CMP-0075627-1, "Header, 100mil, 3x1, Gold, TH", Color=Black, Manufacturer=Samtec
Logo1: library part CMP-0074838-1, "Texas Instrument Corporate Signature"
Logo2: library part CMP-0074844-1
Logo3 Logo5: library part CMP-0074847-1, "FCC_disclaimer"
Logo4: library part CMP-0074769-1
NT1 NT4 NT5: library part CMP-0078142-3, "Single point connection between nets.", Manufacturer=N/A
R1: library part CMP-0026852-2, "RES, 1.0 k, 5%, 0.063 W, 0402", Manufacturer=Vishay-Dale, Power_W=63mW, Supplier Part Number 1=541-1.0KJCT-ND, TempCo="200 ppm/C", Tolerance_%=5%, Value2=0.063W, Value_Code=1k00, ValueDisplayed=1.0k
R2: library part CMP-0024657-2, "RES, 135 k, 0.5%, 0.1 W, 0603", Manufacturer="Yageo America", Power_W=100mW, TempCo="50 ppm/C", Tolerance_%=0.5%, Value2=0.1W, Value_Code=135k
R3: library part CMP-0022712-3, "RES, 0.22, 1%, 0.1 W, AEC-Q200 Grade 0, 0603", Manufacturer=Panasonic, Power_W=100mW, Supplier Part Number 1=P.22AJCT-ND, TempCo="300 ppm/C", Tolerance_%=1%, Value2=0.1W, Value_Code=R220, ValueDisplayed=0.22
R4 R5: library part CMP-0096565-1, "Res Metal Foil 100K Ohm 0.01% 3/5W ±1ppm/°C Molded RDL Thru-Hole Bulk", Digikey Part Number=Y0062-100KA-ND, Manufacturer="Vishay Precision Group", Mouser Part Number=71-S102KT100K00TB, Operating Temperature Range="-55°C to +125°C", Power_W=600mW, TempCo=1ppm/°C, Tolerance_%=0.01%
R6: library part CMP-0023073-5, "RES, 39.0 k, 1%, 0.1 W, 0603", Manufacturer=Yageo, Power_W=100mW, Supplier Part Number 1=311-39.0KHRCT-ND, TempCo="100 ppm/C", Tolerance_%=1%, Value2=0.1W, Value_Code=39k0, ValueDisplayed=39.0k
R7: library part CMP-0025918-5, "RES, 3.3 k, 5%, 0.1 W, 0603", Manufacturer=Yageo, Power_W=100mW, Supplier Part Number 1=311-3.3KGRCT-ND, TempCo="100 ppm/C", Tolerance_%=5%, Value2=0.1W, Value_Code=3k30, ValueDisplayed=3.3k
R8: library part CMP-0016569-3, "RES, 100, 1%, 0.25 W, AEC-Q200 Grade 0, 1206", Manufacturer=Vishay-Dale, Power_W=250mW, Supplier Part Number 1=541-100FCT-ND, TempCo="100 ppm/C", Tolerance_%=1%, Value2=0.25W, Value_Code=100R, ValueDisplayed=100
R9: library part CMP-0018604-3, "RES, 1.1 k, 5%, 0.25 W, AEC-Q200 Grade 0, 1206", Manufacturer=Vishay-Dale, Power_W=250mW, Supplier Part Number 1=541-1.1KECT-ND, TempCo="200 ppm/C", Tolerance_%=5%, Value2=0.25W, Value_Code=1k10, ValueDisplayed=1.1k
RZ12: library part CMP-0020442-3, "RES, 0, 5%, 0.125 W, AEC-Q200 Grade 0, 0805", Manufacturer=Vishay-Dale, Power_W=125mW, Supplier Part Number 1=541-0.0ACT-ND, TempCo="200 ppm/C", Tolerance_%=5%, Value2=0.125W, Value_Code=0000, ValueDisplayed=0
SH-J1 SH-J2: library part CMP-0087961-2, "CONN JUMPER S2 (1 x 2) Position Shunt Connector Black Open Top 0.100\" (2.54mm) GoldHORTING .100\" GOLD", Current_A=3A, Manufacturer=Sullins
U1: library part CMP-0120977-1, "Temperature Compensated Buried Zener Reference With 0.1ppm/°C Drift and 1ppm Stability", Manufacturer="Texas Instruments", Max Supply Voltage=16.5V, Min Supply Voltage=10V, Nominal Supply Current=15mA, Operating Temperature Range="+20°C to +50°C", Output Voltage=7.6V
U2: library part CMP-0070801-2, "3-Terminal Adjustable Regulator, 4-pin SOT-223, Pb-Free", Manufacturer="Texas Instruments", PackageTopMarking=XYTT*N07A, PowerWise=N
U3: library part CMP-0073868-3, "Vin 3V to 36V, 150mA, Ultra-Low-Noise, High-PSRR Low-Dropout (LDO) Linear Regulator, DRB0008A (VSON-8)", Alternate Manufacturer="Texas Instruments", Alternate PartNumber=TPS7A4901DRBT, Operating Temperature Range="-40 to 125 C", Rating=Catalog
ZZ1: library part CMP-0003616-3
ZZ2: library part CMP-0077236-1
ZZ3: library part CMP-0077237-1
ZZ4: library part CMP-0077238-1

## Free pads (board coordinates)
  round 125 hole 125: 7(1713.15,2291.53) 7(1713.15,3266.52) 7(2687.15,2291.53) 7(2687.15,3266.52)
  oval 16x197.5 hole 16 slot 197.5 at 90 deg unplated mask+0.5: m(2561.65,3045.87) ""(1840.65,2506.37) ""(1840.65,3045.87) ""(2561.65,2506.37)
  oval 16x226 hole 16 slot 226 at 90 deg unplated mask+0.5: ""(1840.65,2776.12) ""(2561.65,2776.12)
  oval 16x285 hole 16 slot 285 at 90 deg unplated mask+0.5: ""(1917.65,2679.12) ""(2484.65,2873.12)
  oval 197.5x16 hole 16 slot 197.5 at 0 deg unplated mask+0.5: ""(1931.4,2415.62) ""(1931.4,3136.62) ""(2470.91,2415.62) ""(2470.91,3136.62)
  oval 16x335 hole 16 slot 335 at 90 deg unplated mask+0.5: ""(1969.65,2900.12) ""(2432.65,2652.12)
  oval 335x16 hole 16 slot 335 at 0 deg unplated mask+0.5: ""(2077.15,2544.62) ""(2325.15,3007.62)
  oval 285x16 hole 16 slot 285 at 0 deg unplated mask+0.5: ""(2104.15,3059.62) ""(2298.15,2492.62)
  oval 100x16 hole 16 slot 100 at 0 deg unplated mask+0.5: ""(2138.17,2415.62) ""(2138.17,3136.62) ""(2264.17,2415.62) ""(2264.17,3136.62)

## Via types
v1: diameter 24, hole 12, Top Layer to Bottom Layer, tented both sides, 19 vias
v2: diameter 34, hole 16, Top Layer to Bottom Layer, tented both sides, 9 vias
v3: diameter 24, hole 8, Top Layer to Bottom Layer, tented both sides, 6 vias
v4: diameter 19.68, hole 7.87, Top Layer to Bottom Layer, 4 vias
v5: diameter 16, hole 8, Top Layer to Bottom Layer, tented both sides, 4 vias

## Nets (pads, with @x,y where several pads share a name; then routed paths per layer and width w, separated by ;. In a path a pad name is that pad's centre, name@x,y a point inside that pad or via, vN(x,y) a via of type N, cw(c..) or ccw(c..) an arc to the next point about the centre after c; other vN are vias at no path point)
DIV_OUT: J12.2 R4.1 R5.2 | length 526
  Top Layer w30: J12.2@921.41,2110.17 925.03,2106.55 1115.01,2106.55 R5.2@1118.63,2102.93 1117.66,2101.96 1117.66,1778.89 R4.1@1116.69,1777.91
GND: C1.2 C2.2 C6.2 C9.2 C11.2 C13.2 C14.2 FL1.2 J3.2 J3.3 J3.4 J3.5 J8.5 J10.1 J12.1 J18.2 NT5.1 R2.1 R3.1 R5.1 R7.1 RZ12.1 U1.13 U1.14 U1.15 U3.4 U3.9 | length 3065.3
  Top Layer w6: NT5.1@2172.83,2313.18 v5(2172.83,2329.23)
  Top Layer w10: U1.15@2251.15,2931.63 2260.01,2931.63 U1.14@2301.15,2931.63 ; U1.15@2251.15,2936.12 2251.15,2975.04 2261.73,2985.62 2336,2985.62 v1@2341.15,2980.46
  Top Layer w15: U1.14@2301.15,2931.63 2301.15,2917.56 2304.72,2913.99 v1(2330.66,2913.99)
  Top Layer w20: v1@2341.15,2980.46 v1(2342.15,2979.46) v1(2361.15,2960.46) U1.13@2361.15,2876.12 ; 2356.67,2309.75 2381.13,2309.75
  L02_GND1 w6: v5(2172.83,2329.23) 2172.83,2348.21 2138.37,2382.67 2088.85,2382.67 2067.72,2403.81 2067.72,2466.51 2114.82,2513.62 2250.29,2513.62 2271.29,2534.62 2271.29,2854.62 v1(2330.66,2913.99)
  L03_GND2 w15: 2304.72,3095.54 2304.37,3095.19 2304.37,3052.1 2286.16,3033.88 2150.13,3033.88 2137.26,3021.01 2137.26,2994.26 2151.05,2980.46 2341.15,2980.46 v1(2342.15,2979.46) v1(2361.15,2960.46)
  Bottom Layer w15: v1(2342.15,2979.46) v1(2361.15,2960.46) 2389.99,2931.63 2435.17,2931.63 2460.15,2906.64 2460.15,2728.47 2474.51,2714.12 2503.15,2714.12 2521.65,2732.62 v1(2521.65,2778.3)
  Bottom Layer w30: 2389.99,3271.04 2389.99,3268.74 v1(2439.45,3219.27) ; J3.5@2467.57,4740 J3.4@2812.57,4740 2926.96,4740 3125,4541.96 J18.2@3125,4452.98
  other v1: 2621.25,2071.71 1884.21,2459.17 2518.1,2459.17 1880.65,2776.12 1712.92,2828.11 1884.21,3093.06 2518.1,3093.06 2311.97,3654.02 2310.75,3714.98 2310.75,3753.21
  other v3: 2311.97,3612.37 2023.82,3872.88
  other v4: 2282.44,4252.16 2262.75,4276.77 2302.12,4276.77 2282.44,4301.37
GND_HET: C3.2 C4.2 C15.2 C16.2 C17.2 C18.2 C19.1 FL2.2 J1.2 J2.2 J2.3 J2.4 J2.5 R9.1 RZ12.2 U1.16 U1.17 | length 882.8
  Top Layer w15: 1943.18,3207.12 2015.98,3207.12 2041.62,3181.47 2315.36,3181.47 2334.17,3162.67 2334.17,3065.87 2300.42,3032.12 2137.27,3032.12 2126.16,3021.01 2126.16,2988.7 2144.49,2970.37 2144.89,2970.37 2151.15,2964.11 U1.17@2151.15,2931.63 U1.16@2201.15,2931.63
  other v3: 1592.26,4341.73 1163.45,4375.26 1224.41,4587.26 1567.94,4598.51
HEAT_EXT: C16.1 FL2.3 J1.1 J2.1 J20.1 | length 0
HEAT_LDO: C18.1 D2.2 D3.1 J20.3 R8.2 U2.2 U2.4 | length 408.4
  Top Layer w10: C18.1@832.63,3991.43 864.13,3991.43 894.48,3961.08 J20.3@1039.84,3961.08
  Top Layer w15: R8.2@724.03,4142.05 724.03,3957.61 U2.4@726.98,3954.66
HET+: C3.1 C4.1 J20.2 U1.18 | length 1280.4
  Top Layer w15: v1(2070.48,2936.12) U1.18@2101.15,2936.12
  L02_GND1 w15: v2(1700.11,3582.57) 1703.74,3586.2 1734.16,3586.2 1747.11,3599.15 1842.35,3599.15 2059.19,3382.31 ; 2060.11,3383.23 2059.19,3382.31 ; v1(2070.48,2936.12) 2070.48,2988.7 2116.89,3035.12 2254.81,3035.12 2273.65,3053.96 2273.65,3077.27 2254.82,3096.11 2096.64,3096.11 2059.19,3133.56 2059.19,3382.31
  other v2: 1551.35,3704.96 1553.65,3762.18
LDO: C5.1 C11.1 J17.3 R6.2 U3.1 | length 458.5
  Top Layer w15: C11.1@1941.75,4314.76 C5.1@2041.65,4314.76 ; J17.3@2039.83,4486.75 2041.65,4484.94 C5.1@2041.65,4314.76 ; U3.1@2227.32,4315.15 2215.51,4315.15 2215.12,4314.76 R6.2@2139.34,4314.76 2120.64,4314.76 C5.1@2041.65,4314.76
NetC5_2: C5.2 R6.1 R7.2 U3.2 | length 286.9
  Top Layer w15: C5.2@2041.65,4251.77 2060.35,4251.77 R6.1@2139.34,4251.77 ; R7.2@2139.83,4166.36 2139.83,4231.59 2139.34,4232.08 R6.1@2139.34,4251.77 ; U3.2@2227.32,4289.56 2202.56,4289.56 2171.75,4258.76 2146.33,4258.76 R6.1@2139.34,4251.77
NetC6_1: C6.1 U3.6 | length 74.1
  Top Layer w15: U3.6@2337.56,4263.97 2349.37,4263.97 2349.74,4264.35 C6.1@2411.47,4264.35
NetC7_2: C7.2 C8.2 R3.2 | length 414.9
  Top Layer w10: C7.2@2308.44,1662.11 2308.44,1812.43 2283.37,1837.49 C8.2@2283.66,1982.14 R3.2@2368.1,1982.14
NetC9_1: C9.1 C13.1 FL1.1 U3.5 U3.8 | length 680.5
  Top Layer w15: v2(2337.56,4186.04) U3.5@2337.56,4238.38
  Top Layer w25: 2349.57,4314.95 v2(2396.48,4314.95)
  Top Layer w30: v2(2396.48,4314.95) C9.1@2525.72,4314.95 FL1.1@2704.83,4315.73 2704.83,4244.54 2703.61,4243.32 C13.1@2703.61,4196.67
  Bottom Layer w15: v2(2337.56,4186.04) 2396.48,4244.96 v2(2396.48,4314.95)
NetC15_1: C15.1 C17.1 D2.1 FL2.1 U2.3 | length 606.1
  Top Layer w15: 432.98,3746.41 C15.1@433.09,3746.3
  Top Layer w30: C17.1@319.85,3746.41 432.98,3746.41 ; D2.1@357.15,3864.11 U2.3@480.92,3864.11 C15.1@480.92,3746.3 ; C15.1@433.09,3746.3 C15.1@480.92,3746.3 ; FL2.1@684.3,3746.3 C15.1@480.92,3746.3
NetC19_2: C19.2 D3.2 R8.1 R9.2 U2.1 | length 482.8
  Top Layer w15: D3.2@254.24,4040.29 312.7,4098.75 R9.2@357.09,4098.75 418.91,4098.75 462.22,4142.05 C19.2@480.92,4142.05 ; U2.1@480.92,4045.21 480.92,4122.37 C19.2@480.92,4142.05 ; R8.1@598.05,4142.05 C19.2@480.92,4142.05
NetD1_1: D1.1 R1.1 | length 52
  Top Layer w6: D1.1@1051.45,2945.97 R1.1@1051.45,2997.93
NetR2_2: R2.2 U1.3 | length 1460.3
  Top Layer w15: R2.2@974.77,2437.68 1262.7,2437.68 1743.31,2918.29 1893.18,2918.29 1942.15,2869.32 1942.15,2715.63 1981.67,2676.12 U1.3@2045.64,2676.12
OP-STBL: D1.2 J10.2 U1.20 | length 1549.6
  Top Layer w6: J10.2@1123.07,2729.12 1051.45,2800.74 D1.2@1051.45,2886.92 1067.2,2886.92 1091.12,2863 v1(1422,2863) ; U1.20@2045.64,2826.12 v1(2105.36,2826.12)
  Bottom Layer w6: v1(1422,2863) 1660.72,2863 1716.01,2918.29 1912.19,2918.29 1949.65,2880.83 1949.65,2732.33 1965.2,2716.78 1994.55,2716.78 2103.88,2826.12 v1(2105.36,2826.12)
PWR_EXT: C14.1 FL1.3 J3.1 J17.1 J18.1 | length 100
  Top Layer w15: J3.1@2640.07,4640 J3.1@2640.07,4740
REFZ_F: C7.1 C8.1 J4.1 J6.1 J8.3 J14.1 NT1.1 NT4.1 R4.2 U1.4 | length 5615.8
  Top Layer w6: v2(2051.14,2577.68) 2055.32,2581.86 2094.89,2581.86 U1.4@2101.15,2588.13 ; U1.4@2101.15,2620.61 2101.15,2591.3 2102.74,2589.71 2107.58,2584.87 NT1.1@2114.6,2584.87 ; NT4.1@2147.57,2312.95 v5(2147.57,2329.23)
  Top Layer w10: 2061.75,2355.19 2061.75,2460.55 2120.73,2519.53 2256.2,2519.53 2266.27,2529.6 2266.27,2551.37 2249.85,2567.79 2112.63,2567.79 2102.63,2577.79 2102.63,2586.65 U1.4@2101.15,2588.13
  Top Layer w25: R4.2@1116.69,1627.91 1237.52,1627.91 1305.43,1560 ; J4.1@1140,250 1140,350 1184.11,394.11 J8.3@1184.11,1323.66 1184.11,1438.67 1305.43,1560 ; J6.1@1869.98,384.74 1870.97,385.73 1870.97,1163.23 J14.1@1871.95,1164.22 1874,1166.27 1874,1560 ; 2063.87,2263.99 2101.15,2226.71 2101.15,2099.27 2101.25,2099.17 2101.25,2030.27 2101.25,1925 2101.25,1711.2 2108.99,1703.46 C7.1@2082.12,1676.59 ; C7.1@2082.12,1667.24 2082.12,1574.64 2067.48,1560 1874,1560 ; 1305.43,1560 1874,1560
  L02_GND1 w6: v2(2051.14,2577.68) 2054.05,2580.59 2248.05,2580.59 2259.28,2569.36 2259.28,2538.77 2245.14,2524.62 2105.34,2524.62 2053.6,2472.88 2053.6,2396.04 2082.21,2367.43 2131.65,2367.43 2147.57,2351.52 v5(2147.57,2329.23)
REFZ_S: NT1.2 U1.5 | length 48.9
  Top Layer w6: NT1.2@2134.6,2584.87 2145.36,2584.87 2151.15,2590.66 2151.15,2616.12 U1.5@2151.15,2620.61
REFZ_S_N: J4.2 J4.3 J4.4 J4.5 J8.1 J8.4 J15.1 J16.1 NT5.2 | length 6281.6
  Top Layer w6: v5(2172.83,2267.14) 2168.94,2271.04 2168.94,2289.06 NT5.2@2172.83,2292.95
  Top Layer w6.53: v2(875,250) J4.3@967.5,250 ; J4.2@1312.5,250 v2(1400,250) ; J15.1@2618.01,384.74 J16.1@2618.01,1164.22
  L03_GND2 w6.53: J8.4@1084.11,1323.66 1169.11,1408.66 1299.11,1408.66 J8.1@1384.11,1323.66
  Bottom Layer w6.53: v2(875,250) J4.4@967.5,250 J4.5@1312.5,250 ; v2(1400,250) J4.5@1312.5,250 ; v5(2172.83,2267.14) 2172.83,2092.07 2222.14,2042.76 2222.14,1483.01 ; J15.1@2618.01,384.74 J16.1@2618.01,1164.22 2618.01,1423.99 2581,1461 2246,1461 2223.99,1483.01 2222.14,1483.01 ; J4.5@1312.5,250 1312.5,350 1320.55,358.05 1320.55,428.59 1384.11,492.14 J8.1@1384.11,1323.66 1338.95,1368.81 1338.95,1430.04 1376.07,1467.16 2206.29,1467.16 2222.14,1483.01
REFZ_S_P: J8.2 NT4.2 | length 1852.6
  Top Layer w6: v5(2147.04,2267.14) 2150.94,2271.04 2150.94,2289.06 NT4.2@2147.04,2292.95
  Bottom Layer w6: v5(2147.04,2267.14) 2150.94,2263.24 2150.94,2212.09
  Bottom Layer w6.53: J8.2@1284.11,1323.66 1284.11,1332.18 1320.55,1368.63 1320.55,1441.58 1365.89,1486.92 2185.83,1486.92 2197.12,1498.22 2197.12,1538.4 2199.19,2036.7 2150.94,2084.95 2150.94,2212.09
VDD: C1.1 C2.1 J17.2 R1.2 U1.19 | length 3292.2
  Top Layer w15: R1.2@1098.7,2997.93 1098.7,2986.12 1100.08,2984.75 1100.08,2976.96 1141.05,2935.98 v2(1623.19,2935.98) ; U1.19@2041.15,2876.12 v1(2041.15,2906.8)
  L02_GND1 w15: v2(1623.19,2935.98) 1623.78,2935.98 1641.48,2918.29 1893.18,2918.29 1945.15,2866.32 1945.15,2723.74 1963.41,2705.48 2019.13,2705.48 2041.15,2727.51 v1(2041.15,2906.8)
  Bottom Layer w15: v1(2041.15,2906.8) 2041.15,2994.05 2082.22,3035.12 2291.68,3035.12 2346.23,3089.67 2346.23,3198.76 2192.65,3352.34 2192.65,3441.4 2192.65,3521.55 2192.65,3619.32 2192.65,3734.98 2192.65,4433.93 J17.2@2139.83,4486.75
pads on no net: FID1.1 FID2.1 FID3.1 H1.1 H2.1 H3.1 H4.1 H5.0 H6.0 H7.0 H8.0 U1.1 U1.2 U1.6 U1.7 U1.8 U1.9 U1.10 U1.11 U1.12 U3.3 U3.7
